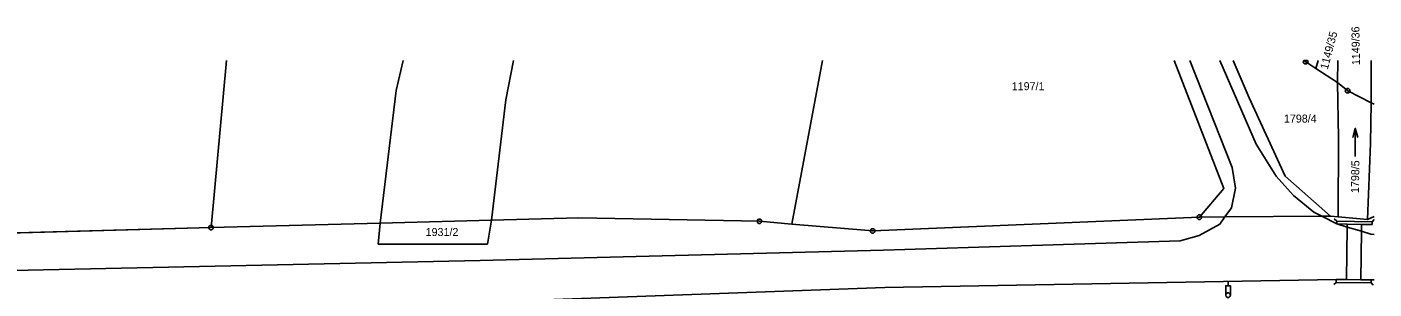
# Model space of a CAD drawing. Extents: x -777309 to -774195, y -1144706 to -1143600.
# Drawn here: x -776386.1 to -776100, y -1143848.6 to -1143792.9 of the extents above; entities that cross this region are included whole.
import ezdxf

# ---------------------------------------------------------------- set-up
doc = ezdxf.new("R2010")
doc.units = 0
for name, color, linetype in [('1', 7, 'Continuous'), ('11', 7, 'Continuous'), ('2', 7, 'Continuous'), ('3', 7, 'Continuous'), ('4', 7, 'Continuous'), ('6', 7, 'Continuous'), ('8', 7, 'Continuous')]:
    doc.layers.add(name, color=color, linetype=linetype)

msp = doc.modelspace()

# ---------------------------------------------------------------- linework, layer by layer
at = {"layer": '1'}
for p, q in [((-776343.72, -1143800), (-776347.03, -1143835.55)), ((-776307.69, -1143806.41), (-776306.21, -1143800)), ((-776282.77, -1143800), (-776284.43, -1143808.41)), ((-776223.65, -1143834.8), (-776217.16, -1143800)), ((-776142.45, -1143800), (-776131.92, -1143827.25)), ((-776129.94, -1143800), (-776126.54, -1143807.93)), ((-776114.52, -1143800.29), (-776114.9, -1143800)), ((-776114.52, -1143800.29), (-776114.42, -1143800)), ((-776114.52, -1143800.29), (-776112.4, -1143801.68)), ((-776112.4, -1143801.68), (-776111.84, -1143800)), ((-776112.4, -1143801.68), (-776107.74, -1143804.72)), ((-776107.72, -1143800), (-776107.74, -1143804.72)), ((-776100.59, -1143800), (-776100.61, -1143809)), ((-776311.1, -1143834.59), (-776307.69, -1143806.41)), ((-776107.55, -1143816.45), (-776107.74, -1143804.72)), ((-776105.6, -1143806.46), (-776107.74, -1143804.72)), ((-776105.6, -1143806.46), (-776100.61, -1143809)), ((-776284.43, -1143808.41), (-776287.47, -1143833.95)), ((-776126.54, -1143807.93), (-776118.9, -1143824.61)), ((-776100.61, -1143809), (-776100.78, -1143817.69)), ((-776100, -1143809.31), (-776100.61, -1143809)), ((-776107.6, -1143833.25), (-776107.55, -1143816.45)), ((-776100.78, -1143817.69), (-776101.4, -1143833.8)), ((-776118.9, -1143824.61), (-776109.27, -1143833.1)), ((-776131.92, -1143827.25), (-776137.1, -1143833.33)), ((-776131.67, -1143833.29), (-776111.12, -1143833.12)), ((-776111.12, -1143833.12), (-776109.27, -1143833.1)), ((-776107.6, -1143833.25), (-776109.27, -1143833.1)), ((-776101.4, -1143833.8), (-776100, -1143833.22)), ((-776421.99, -1143837.57), (-776347.03, -1143835.55)), ((-776311.1, -1143834.59), (-776347.03, -1143835.55)), ((-776311.1, -1143834.59), (-776311.54, -1143839.07)), ((-776287.47, -1143833.95), (-776311.1, -1143834.59)), ((-776288.34, -1143839.05), (-776287.47, -1143833.95)), ((-776287.47, -1143833.95), (-776268.92, -1143833.45)), ((-776230.55, -1143834.21), (-776268.92, -1143833.45)), ((-776223.65, -1143834.8), (-776230.55, -1143834.21)), ((-776207.34, -1143836.19), (-776223.65, -1143834.8)), ((-776137.1, -1143833.33), (-776206.49, -1143836.26)), ((-776137.1, -1143833.33), (-776131.67, -1143833.29)), ((-776107.6, -1143833.25), (-776101.4, -1143833.8)), ((-776206.49, -1143836.26), (-776207.34, -1143836.19)), ((-776311.54, -1143839.07), (-776288.34, -1143839.05))]:
    msp.add_line(p, q, dxfattribs=at)
at = {"layer": '11'}
for points in [[(-776534.92, -1143800), (-776538.12, -1143839.04), (-776516.26, -1143840.11), (-776511.15, -1143839.97), (-776489.11, -1143839.38), (-776472.47, -1143838.93), (-776439.72, -1143838.05), (-776421.99, -1143837.57), (-776347.03, -1143835.55), (-776311.1, -1143834.59), (-776287.47, -1143833.95), (-776268.92, -1143833.45), (-776230.55, -1143834.21)], [(-776230.55, -1143834.21), (-776223.65, -1143834.8), (-776207.34, -1143836.19), (-776206.49, -1143836.26), (-776137.1, -1143833.33), (-776131.92, -1143827.25), (-776142.45, -1143800)], [(-776100, -1143833.22), (-776101.4, -1143833.8), (-776100.78, -1143817.69), (-776100.61, -1143809), (-776100.59, -1143800)]]:
    msp.add_lwpolyline(points, dxfattribs=at)
at = {"layer": '3'}
msp.add_line((-776103.98, -1143820.42), (-776103.98, -1143814.42), dxfattribs=at)
msp.add_lwpolyline([(-776104.48, -1143816.42), (-776103.98, -1143814.42), (-776103.48, -1143816.42)], dxfattribs=at)
at = {"layer": '4'}
for p, q in [((-776139.14, -1143800), (-776130.15, -1143822.78)), ((-776125.04, -1143817.78), (-776132.78, -1143800)), ((-776120.79, -1143824.58), (-776125.04, -1143817.78)), ((-776129.46, -1143827.18), (-776130.15, -1143822.78)), ((-776117.11, -1143828.71), (-776120.79, -1143824.58)), ((-776130.31, -1143831.36), (-776129.46, -1143827.18)), ((-776112.78, -1143832.25), (-776117.11, -1143828.71)), ((-776131.67, -1143833.29), (-776130.31, -1143831.36)), ((-776112.78, -1143832.25), (-776111.12, -1143833.12)), ((-776111.12, -1143833.12), (-776107.94, -1143834.78)), ((-776132.76, -1143834.84), (-776137.16, -1143837.26)), ((-776132.76, -1143834.84), (-776131.67, -1143833.29)), ((-776107.94, -1143834.17), (-776108.46, -1143833.69)), ((-776107.94, -1143834.78), (-776107.94, -1143834.17)), ((-776107.94, -1143834.17), (-776100.41, -1143834.3)), ((-776105.71, -1143834.82), (-776107.94, -1143834.78)), ((-776105.72, -1143835.44), (-776107.94, -1143834.78)), ((-776105.72, -1143835.44), (-776105.84, -1143846.62)), ((-776105.71, -1143834.82), (-776105.72, -1143835.44)), ((-776102.69, -1143836.34), (-776105.72, -1143835.44)), ((-776102.67, -1143834.87), (-776105.71, -1143834.82)), ((-776102.69, -1143836.34), (-776102.67, -1143834.87)), ((-776100.42, -1143834.91), (-776102.67, -1143834.87)), ((-776100.41, -1143834.3), (-776100.42, -1143834.91)), ((-776100.41, -1143834.3), (-776100, -1143833.83)), ((-776204.2, -1143840.35), (-776141.21, -1143838.36)), ((-776141.21, -1143838.36), (-776137.16, -1143837.26)), ((-776102.84, -1143846.65), (-776102.69, -1143836.34)), ((-776100.66, -1143836.94), (-776102.69, -1143836.34)), ((-776100.66, -1143836.94), (-776100, -1143837.01)), ((-776289.89, -1143842.57), (-776204.2, -1143840.35)), ((-776289.89, -1143842.57), (-776429.58, -1143845.53)), ((-776203.92, -1143848.29), (-776108.04, -1143846.61)), ((-776108.04, -1143847.21), (-776108.57, -1143847.68)), ((-776108.04, -1143847.21), (-776108.04, -1143846.61)), ((-776108.04, -1143846.61), (-776105.84, -1143846.62)), ((-776100.62, -1143847.26), (-776108.04, -1143847.21)), ((-776105.84, -1143846.62), (-776102.84, -1143846.65)), ((-776102.84, -1143846.65), (-776100.62, -1143846.66)), ((-776100, -1143846.65), (-776100.62, -1143846.66)), ((-776100.62, -1143846.66), (-776100.62, -1143847.26)), ((-776100.62, -1143847.26), (-776100.19, -1143847.82)), ((-776285.88, -1143851.28), (-776203.92, -1143848.29))]:
    msp.add_line(p, q, dxfattribs=at)
at = {"layer": '6'}
msp.add_line((-776131, -1143847.92), (-776131, -1143846.92), dxfattribs=at)
msp.add_lwpolyline([(-776130.5, -1143849.92), (-776130.6, -1143850.21), (-776130.85, -1143850.39), (-776131.16, -1143850.39), (-776131.41, -1143850.21), (-776131.51, -1143849.92), (-776131.41, -1143849.63), (-776131.16, -1143849.45), (-776130.85, -1143849.45), (-776130.6, -1143849.63), (-776130.5, -1143849.92), (-776130.5, -1143848.65), (-776130.5, -1143847.92), (-776131, -1143847.92), (-776131.5, -1143847.92), (-776131.5, -1143849.19), (-776131.5, -1143849.92)], dxfattribs=at)
at = {"layer": '8'}
for p, q in [((-776114.12, -1143800), (-776114.93, -1143800)), ((-776114.64, -1143800.29), (-776114.4, -1143800.29)), ((-776105.72, -1143806.46), (-776105.48, -1143806.46)), ((-776347.15, -1143835.55), (-776346.91, -1143835.55)), ((-776230.67, -1143834.21), (-776230.43, -1143834.21)), ((-776137.22, -1143833.33), (-776136.98, -1143833.33)), ((-776206.61, -1143836.26), (-776206.37, -1143836.26))]:
    msp.add_line(p, q, dxfattribs=at)
msp.add_lwpolyline([(-776114.93, -1143800), (-776115.03, -1143800.28), (-776114.93, -1143800.57), (-776114.68, -1143800.75), (-776114.37, -1143800.75), (-776114.12, -1143800.57), (-776114.02, -1143800.28), (-776114.12, -1143800)], dxfattribs=at)
for points in [[(-776105.45, -1143805.98), (-776105.2, -1143806.16), (-776105.1, -1143806.45), (-776105.2, -1143806.74), (-776105.45, -1143806.92), (-776105.76, -1143806.92), (-776106.01, -1143806.74), (-776106.11, -1143806.45), (-776106.01, -1143806.16), (-776105.76, -1143805.98)], [(-776136.95, -1143832.85), (-776136.7, -1143833.03), (-776136.6, -1143833.32), (-776136.7, -1143833.61), (-776136.95, -1143833.79), (-776137.26, -1143833.79), (-776137.51, -1143833.61), (-776137.61, -1143833.32), (-776137.51, -1143833.03), (-776137.26, -1143832.85)], [(-776346.88, -1143835.07), (-776346.63, -1143835.25), (-776346.53, -1143835.54), (-776346.63, -1143835.83), (-776346.88, -1143836.01), (-776347.19, -1143836.01), (-776347.44, -1143835.83), (-776347.54, -1143835.54), (-776347.44, -1143835.25), (-776347.19, -1143835.07)], [(-776230.4, -1143833.73), (-776230.15, -1143833.91), (-776230.05, -1143834.2), (-776230.15, -1143834.49), (-776230.4, -1143834.67), (-776230.71, -1143834.67), (-776230.96, -1143834.49), (-776231.06, -1143834.2), (-776230.96, -1143833.91), (-776230.71, -1143833.73)], [(-776206.34, -1143835.78), (-776206.09, -1143835.96), (-776205.99, -1143836.25), (-776206.09, -1143836.54), (-776206.34, -1143836.72), (-776206.65, -1143836.72), (-776206.9, -1143836.54), (-776207, -1143836.25), (-776206.9, -1143835.96), (-776206.65, -1143835.78)]]:
    msp.add_lwpolyline(points, close=True, dxfattribs=at)

# ---------------------------------------------------------------- texts
at = {"layer": '2'}
for s, rotation, p in [('1149/36', 90.9857, (-776102.98, -1143800.98)), ('1149/35', 75.2867, (-776109.85, -1143802.04)), ('1798/5', 88.9803, (-776103.23, -1143828.21))]:
    msp.add_text(s, height=1.7, rotation=rotation, dxfattribs=at).set_placement(p)
for s, p in [('1197/1', (-776176.96, -1143806.32)), ('1798/4', (-776119.14, -1143813.21)), ('1931/2', (-776301.45, -1143837.34))]:
    msp.add_text(s, height=1.7, dxfattribs=at).set_placement(p)

doc.saveas('drawing.dxf')
